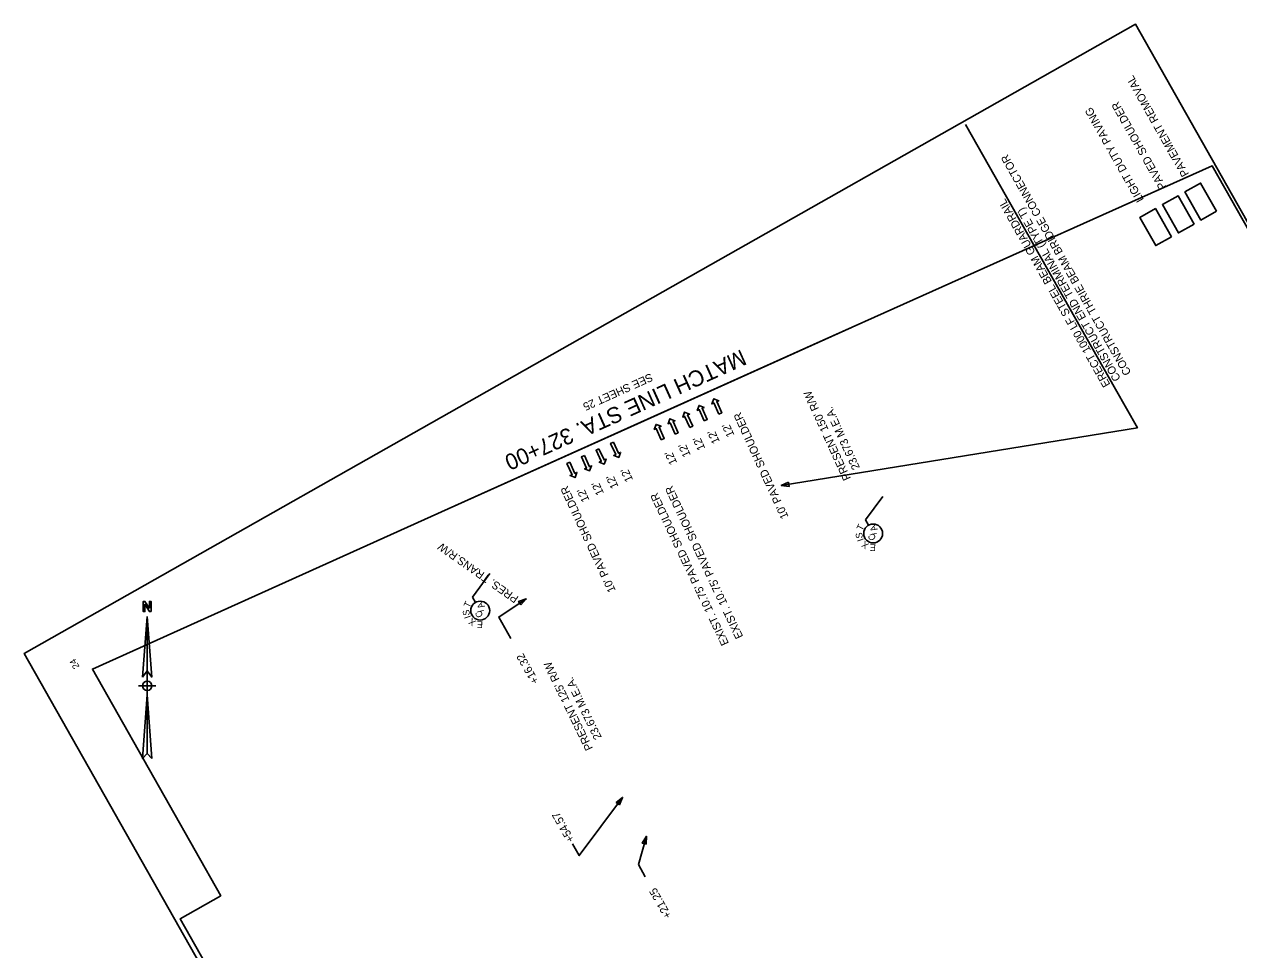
# Model space of a CAD drawing. Extents: x 1612404 to 1614220, y 1085556 to 1087485.
# Drawn here: x 1612526 to 1613435, y 1086792 to 1087485 of the extents above; entities that cross this region are included whole.
import ezdxf

# ---------------------------------------------------------------- set-up
doc = ezdxf.new("R2010")
doc.units = 0
for name, color, linetype in [('RD_EX_BldgApp', 7, 'Continuous'), ('RD_EX_Driveway', 7, 'Continuous'), ('RD_EX_DV_TX_Gov', 7, 'Continuous'), ('RD_EX_Fence_Other', 7, 'Continuous'), ('RD_EX_Misc', 7, 'Continuous'), ('RD_EX_Misc_Golf_Teebox', 7, 'Continuous'), ('RD_EX_RailRoad', 7, 'Continuous'), ('RD_EX_UT', 7, 'Continuous'), ('RD_EX_VEG', 7, 'Continuous')]:
    doc.layers.add(name, color=color, linetype=linetype)

msp = doc.modelspace()

# ---------------------------------------------------------------- linework, layer by layer
at = {"layer": 'RD_EX_BldgApp'}
for points in [[(1612890.09, 1087024.77), (1612880.95, 1087040.91), (1612901.55, 1087054.48)], [(1612936.26, 1086870.91), (1612941.2, 1086862.19), (1612973.69, 1086905.78)], [(1612990.7, 1086846.35), (1612985.54, 1086855.46), (1612991.57, 1086876.67)]]:
    msp.add_lwpolyline(points, dxfattribs=at)
for points in [[(1612897.57, 1087050), (1612901.55, 1087054.48), (1612895.86, 1087052.59)], [(1612971.48, 1086900.2), (1612973.69, 1086905.78), (1612968.99, 1086902.06)], [(1612991.48, 1086870.67), (1612991.57, 1086876.67), (1612988.49, 1086871.52)]]:
    msp.add_lwpolyline(points, close=True, dxfattribs=at)
at = {"layer": 'RD_EX_Driveway'}
msp.add_line((1613230.6, 1087409.98), (1613342.97, 1087211.51), dxfattribs=at)
msp.add_lwpolyline([(1613342.97, 1087211.51), (1613359.28, 1087182.71), (1613092.57, 1087139.4)], dxfattribs=at)
msp.add_lwpolyline([(1613098.04, 1087141.86), (1613092.57, 1087139.4), (1613098.54, 1087138.79)], close=True, dxfattribs=at)
at = {"layer": 'RD_EX_DV_TX_Gov'}
for p, q in [((1613155.64, 1087113.67), (1613168.58, 1087131.28)), ((1613157.89, 1087109.69), (1613155.64, 1087113.67)), ((1612861.32, 1087055.89), (1612874.26, 1087073.5)), ((1612863.57, 1087051.91), (1612861.32, 1087055.89))]:
    msp.add_line(p, q, dxfattribs=at)
for centre in [(1613161.39, 1087103.52), (1612867.07, 1087045.74)]:
    msp.add_circle(centre, 7.08, dxfattribs=at)
at = {"layer": 'RD_EX_Fence_Other'}
msp.add_lwpolyline([(1613350.79, 1085556.09), (1612525.56, 1087013.71), (1613357.93, 1087484.95), (1614183.15, 1086027.33)], close=True, dxfattribs=at)
at = {"layer": 'RD_EX_Misc'}
for points in [[(1613045.84, 1087192.97), (1613048.03, 1087193.97), (1613044.21, 1087202.31), (1613045.69, 1087202.99), (1613041.94, 1087204.38), (1613040.55, 1087200.63), (1613042.03, 1087201.31)], [(1613024.02, 1087182.98), (1613026.2, 1087183.98), (1613022.39, 1087192.32), (1613023.87, 1087193), (1613020.12, 1087194.4), (1613018.72, 1087190.65), (1613020.2, 1087191.32)], [(1613034.93, 1087187.98), (1613037.11, 1087188.98), (1613033.3, 1087197.32), (1613034.78, 1087197.99), (1613031.03, 1087199.39), (1613029.64, 1087195.64), (1613031.12, 1087196.32)], [(1613002.68, 1087173.77), (1613004.86, 1087174.77), (1613001.05, 1087183.11), (1613002.53, 1087183.79), (1612998.78, 1087185.18), (1612997.38, 1087181.43), (1612998.86, 1087182.11)], [(1613013.11, 1087177.99), (1613015.29, 1087178.99), (1613011.47, 1087187.33), (1613012.96, 1087188.01), (1613009.21, 1087189.4), (1613007.81, 1087185.65), (1613009.29, 1087186.33)], [(1612955.99, 1087166.9), (1612953.81, 1087165.89), (1612957.66, 1087157.57), (1612956.18, 1087156.88), (1612959.93, 1087155.5), (1612961.32, 1087159.26), (1612959.84, 1087158.57)], [(1612966.89, 1087171.93), (1612964.71, 1087170.92), (1612968.55, 1087162.6), (1612967.08, 1087161.91), (1612970.83, 1087160.53), (1612972.21, 1087164.29), (1612970.73, 1087163.6)], [(1612934.2, 1087156.84), (1612932.02, 1087155.84), (1612935.87, 1087147.51), (1612934.39, 1087146.83), (1612938.14, 1087145.44), (1612939.53, 1087149.2), (1612938.05, 1087148.51)], [(1612945.1, 1087161.87), (1612942.92, 1087160.87), (1612946.76, 1087152.54), (1612945.28, 1087151.86), (1612949.04, 1087150.47), (1612950.42, 1087154.23), (1612948.94, 1087153.54)]]:
    msp.add_lwpolyline(points, close=True, dxfattribs=at)
at = {"layer": 'RD_EX_Misc_Golf_Teebox'}
for points in [[(1613418.62, 1087344.91), (1613406.66, 1087366.03), (1613394.96, 1087359.4), (1613406.91, 1087338.29)], [(1613401.71, 1087335.34), (1613389.75, 1087356.46), (1613378.05, 1087349.83), (1613390, 1087328.71)], [(1613384.8, 1087325.77), (1613372.84, 1087346.88), (1613361.14, 1087340.25), (1613373.09, 1087319.14)]]:
    msp.add_lwpolyline(points, close=True, dxfattribs=at)
for points in [[(1613418.62, 1087344.91), (1613406.66, 1087366.03), (1613394.96, 1087359.4), (1613406.91, 1087338.29), (1613418.62, 1087344.91)], [(1613401.71, 1087335.34), (1613389.75, 1087356.46), (1613378.05, 1087349.83), (1613390, 1087328.71), (1613401.71, 1087335.34)], [(1613384.8, 1087325.77), (1613372.84, 1087346.88), (1613361.14, 1087340.25), (1613373.09, 1087319.14), (1613384.8, 1087325.77)]]:
    msp.add_lwpolyline(points, dxfattribs=at)
at = {"layer": 'RD_EX_RailRoad'}
for p, q in [((1612617.62, 1087041.25), (1612614.21, 1086995.93)), ((1612617.63, 1087000.58), (1612614.21, 1086995.93)), ((1612617.63, 1087000.58), (1612617.62, 1086982.74)), ((1612624.15, 1086989.36), (1612611.17, 1086989.36)), ((1612617.62, 1086982.74), (1612621.04, 1086934.9)), ((1612621.04, 1086934.9), (1612617.62, 1086938.73))]:
    msp.add_line(p, q, dxfattribs=at)
msp.add_lwpolyline([(1612620.56, 1087045.07), (1612619.33, 1087045.07), (1612615.92, 1087050.54), (1612615.92, 1087049.72), (1612615.92, 1087045.07), (1612614.69, 1087045.07), (1612614.69, 1087052.66), (1612615.92, 1087052.66), (1612619.33, 1087047.6), (1612619.33, 1087048.01), (1612619.33, 1087052.66), (1612620.56, 1087052.66), (1612620.56, 1087045.07)], dxfattribs=at)
for points in [[(1612617.62, 1087041.25), (1612621.04, 1086995.93), (1612617.63, 1087000.58)], [(1612617.62, 1086982.74), (1612617.62, 1086938.73), (1612614.21, 1086934.9)]]:
    msp.add_lwpolyline(points, close=True, dxfattribs=at)
msp.add_circle((1612617.66, 1086989.36), 3.45, dxfattribs=at)
at = {"layer": 'RD_EX_UT'}
msp.add_lwpolyline([(1613343.67, 1085653.32), (1614126.43, 1086125.05), (1613415.21, 1087379.03), (1613116.66, 1087245.07), (1612843.09, 1087121.93), (1612576.55, 1087001.95), (1612672.66, 1086832.08), (1612642.38, 1086814.95), (1613299.85, 1085652.9)], close=True, dxfattribs=at)
msp.add_lwpolyline([(1613343.67, 1085653.32), (1614126.43, 1086125.05), (1613415.21, 1087379.03), (1613116.66, 1087245.07), (1612843.09, 1087121.93), (1612576.55, 1087001.95), (1612672.66, 1086832.08), (1612642.38, 1086814.95), (1613299.85, 1085652.9)], close=True, dxfattribs=at)
msp.add_lwpolyline([(1613343.67, 1085653.32), (1614126.43, 1086125.05), (1613415.21, 1087379.03), (1613116.66, 1087245.07), (1612843.09, 1087121.93), (1612576.55, 1087001.95), (1612672.66, 1086832.08), (1612642.38, 1086814.95), (1613299.85, 1085652.9)], close=True, dxfattribs=at)
at = {"layer": 'RD_EX_VEG'}
msp.add_lwpolyline([(1613145.08, 1087257.86), (1612979.88, 1087183.5), (1612843.09, 1087121.93)], dxfattribs=at)

# ---------------------------------------------------------------- texts
at = {"layer": 'RD_EX_BldgApp'}
for s, rotation, p in [("PRESENT 150' R/W ", 114.58745, (1613144.82, 1087144.84)), ('  23.673 M.E.A.', 114.58745, (1613153.46, 1087148.79)), ('PRES. TRANS.R/W', 144.7665, (1612896.3, 1087055.85)), ('+16.32', 119.51633, (1612911.25, 1086992.78)), ("PRESENT 125' R/W ", 115.93871, (1612951.65, 1086942.66)), ('  23.673 M.E.A.', 115.93871, (1612960.19, 1086946.82)), ('+54.57', 119.51633, (1612937.89, 1086874.13)), ('+21.25', 119.51633, (1613010.68, 1086817.14))]:
    msp.add_text(s, height=6, rotation=rotation, dxfattribs=at).set_placement(p)
at = {"layer": 'RD_EX_Driveway'}
for s, p in [('CONSTRUCT THRIE BEAM BRIDGE CONNECTOR', (1613354.87, 1087223.99)), ('ERECT 1000 LF STEEL BEAM GUARDRAIL', (1613339.2, 1087215.12)), ('CONSTRUCT END TERMINAL (TYPE T)', (1613347.04, 1087219.55))]:
    msp.add_text(s, height=6, rotation=119.51796, dxfattribs=at).set_placement(p)
at = {"layer": 'RD_EX_DV_TX_Gov'}
for s, rotation, p in [('T', 62.56641, (1613153.13, 1087105.15)), ('A', 119.51308, (1613164.97, 1087106.63)), ('S', 97.72789, (1613153.7, 1087100.09)), ('C', 119.51308, (1613163.87, 1087099.92)), ('/', 119.51308, (1613164.25, 1087103.54)), ('I', 109.44838, (1613154.55, 1087098.6)), ('X', 144.60985, (1613158.63, 1087095.56)), ('E', 178.09697, (1613163.48, 1087095.36)), ('T', 62.56641, (1612858.8, 1087047.37)), ('A', 119.51308, (1612870.65, 1087048.85)), ('S', 97.72789, (1612859.37, 1087042.32)), ('I', 109.44838, (1612860.23, 1087040.83)), ('X', 144.60985, (1612864.31, 1087037.79)), ('C', 119.51308, (1612869.55, 1087042.15)), ('/', 119.51308, (1612869.93, 1087045.76)), ('E', 178.09697, (1612869.16, 1087037.59))]:
    msp.add_text(s, height=5, rotation=rotation, dxfattribs=at).set_placement(p)
at = {"layer": 'RD_EX_Misc_Golf_Teebox'}
for s, height, rotation, p in [('PAVEMENT REMOVAL', 6, 119.51633, (1613398.15, 1087372.8)), ('LIGHT DUTY PAVING', 6, 119.51633, (1613364.33, 1087353.65)), ('PAVED SHOULDER', 6, 119.51633, (1613381.24, 1087363.23)), ("10' PAVED SHOULDER", 6, 114.58528, (1613098.13, 1087116.05)), ("12'", 6, 114.58366, (1613057.6, 1087177.3)), ("12'", 6, 114.58366, (1613035.77, 1087167.31)), ("12'", 6, 114.58366, (1613046.68, 1087172.31)), ("12'", 6, 114.58366, (1613024.86, 1087162.32)), ("12'", 6, 114.58366, (1613014.68, 1087156.56)), ("12'", 6, 114.77918, (1612970.77, 1087138.71)), ("12'", 6, 114.77918, (1612981.67, 1087143.74)), ("10' PAVED SHOULDER", 6, 114.78081, (1612968.7, 1087060.97)), ("12'", 6, 114.77918, (1612959.88, 1087133.68)), ("EXIST. 10.75' PAVED SHOULDER", 6, 115.20282, (1613064.13, 1087026.31)), ("12'", 6, 114.77918, (1612948.98, 1087128.65)), ("EXIST. 10.75' PAVED SHOULDER", 6, 115.42129, (1613053.47, 1087021.28)), ('24', 5, 119.51633, (1612567.12, 1087003.74))]:
    msp.add_text(s, height=height, rotation=rotation, dxfattribs=at).set_placement(p)
at = {"layer": 'RD_EX_VEG'}
for s, height, p in [('MATCH LINE STA. 327+00', 12, (1613062.74, 1087241.63)), ('SEE SHEET 25', 6, (1612994.68, 1087223.75))]:
    msp.add_text(s, height=height, rotation=204.23352, dxfattribs=at).set_placement(p)

doc.saveas('drawing.dxf')
